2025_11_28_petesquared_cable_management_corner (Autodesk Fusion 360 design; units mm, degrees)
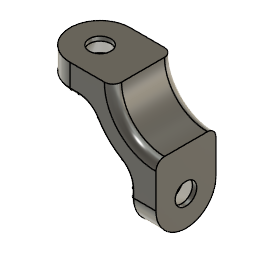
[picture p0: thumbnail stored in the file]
derived_base_feature "Derived Base Feature" bodies "cubby_printer_top", "cubby_printer_side_right"
sketch "cable_bracket_front" plane through (254.762, 0, 0) normal (-1, 0, 0) x axis (0, -1, 0)
  line L1 (0, 15.4952) -> (0, -58.801)
  line L2 (-190.6736, 294.1908) -> (-9.7162, 45.3743)
  line L3 (-9.7162, 662.5237) -> (-190.6736, 413.7072)
  line L4 (0, 766.699) -> (0, 692.4028)
  line L5 (-12.954, 773.049) -> (-6.35, 773.049)
  line L6 (-12.954, 760.095) -> (-12.954, 773.049)
  line L7 (-19.304, 760.095) -> (-12.954, 760.095)
  line L8 (-19.304, 692.4028) -> (-19.304, 760.095)
  line L9 (-31.496, 692.4028) -> (-19.304, 692.4028)
  line L10 (-31.496, 760.095) -> (-31.496, 692.4028)
  line L11 (-584.454, 760.095) -> (-31.496, 760.095)
  line L12 (-584.454, 683.641) -> (-584.454, 760.095)
  line L13 (-596.646, 683.641) -> (-584.454, 683.641)
  line L14 (-596.646, -52.197) -> (-596.646, 683.641)
  line L15 (-12.954, -52.197) -> (-596.646, -52.197)
  line L16 (-12.954, -65.151) -> (-12.954, -52.197)
  line L17 (-6.35, -65.151) -> (-12.954, -65.151)
  line L18 (-583.946, 594.8881) -> (-583.946, 113.0099)
  line L19 (-362.7757, 368.8886) -> (-538.0041, 609.8276)
  line L20 (-538.0041, 98.0704) -> (-362.7757, 339.0094)
  line L21 (-496.0214, 681.6554) -> (-325.3419, 446.9711)
  line L22 (-134.1205, 721.995) -> (-475.4795, 721.995)
  line L23 (-284.2581, 446.9711) -> (-113.5786, 681.6554)
  line L24 (-325.3419, 260.9269) -> (-468.3123, 64.3426)
  line L25 (-141.2877, 64.3426) -> (-284.2581, 260.9269)
  line L26 (-447.7704, 24.003) -> (-161.8296, 24.003)
  line L27 (-128.905, 754.761) -> (-137.795, 754.761)
  line L28 (-128.905, 748.411) -> (-128.905, 754.761)
  line L29 (-137.795, 748.411) -> (-137.795, 754.761)
  line L30 (-128.905, 748.411) -> (-133.35, 748.411)
  line L31 (-137.795, 748.411) -> (-133.35, 748.411)
  line L32 (-133.35, 754.761) -> (-133.35, 748.411)
  line L33 (-128.905, 750.697) -> (-137.795, 750.697)
  line L34 (-31.496, 761.111) -> (-585.216, 761.111)
  arc A1 centre (-6.35, -58.801) radius 6.35 clockwise from (0, -58.801) to (-6.35, -65.151)
  arc A2 centre (-50.8, 15.4952) radius 50.8 clockwise from (-9.7162, 45.3743) to (0, 15.4952)
  arc A3 centre (-108.5061, 353.949) radius 101.6 clockwise from (-190.6736, 294.1908) to (-190.6736, 413.7072)
  arc A4 centre (-50.8, 692.4028) radius 50.8 clockwise from (0, 692.4028) to (-9.7162, 662.5237)
  arc A5 centre (-6.35, 766.699) radius 6.35 clockwise from (-6.35, 773.049) to (0, 766.699)
  circle C1 centre (-76.2, 748.411) radius 1.6002
  circle C2 centre (-133.35, 748.411) radius 1.6002
  circle C3 centre (-190.5, 748.411) radius 1.6002
  circle C4 centre (-247.65, 748.411) radius 1.6002
  circle C5 centre (-361.95, 748.411) radius 1.6002
  circle C6 centre (-419.1, 748.411) radius 1.6002
  circle C7 centre (-476.25, 748.411) radius 1.6002
  circle C8 centre (-533.4, 748.411) radius 1.6002
  circle C9 centre (-304.8, 748.411) radius 1.6002
  circle C10 centre (-533.4, 11.049) radius 8.128
  arc A6 centre (-558.546, 113.0099) radius 25.4 clockwise from (-538.0041, 98.0704) to (-583.946, 113.0099)
  arc A7 centre (-558.546, 594.8881) radius 25.4 clockwise from (-583.946, 594.8881) to (-538.0041, 609.8276)
  arc A8 centre (-383.3176, 353.949) radius 25.4 clockwise from (-362.7757, 368.8886) to (-362.7757, 339.0094)
  arc A9 centre (-304.8, 461.9107) radius 25.4 clockwise from (-284.2581, 446.9711) to (-325.3419, 446.9711)
  arc A10 centre (-475.4795, 696.595) radius 25.4 clockwise from (-496.0214, 681.6554) to (-475.4795, 721.995)
  arc A11 centre (-134.1205, 696.595) radius 25.4 clockwise from (-134.1205, 721.995) to (-113.5786, 681.6554)
  circle C11 centre (-533.4, 696.849) radius 8.128
  circle C12 centre (-76.2, 11.049) radius 8.128
  circle C13 centre (-76.2, 696.849) radius 8.128
  arc A12 centre (-447.7704, 49.403) radius 25.4 clockwise from (-447.7704, 24.003) to (-468.3123, 64.3426)
  arc A13 centre (-304.8, 245.9873) radius 25.4 clockwise from (-325.3419, 260.9269) to (-284.2581, 260.9269)
  arc A14 centre (-161.8296, 49.403) radius 25.4 clockwise from (-141.2877, 64.3426) to (-161.8296, 24.003)
  circle C14 centre (-133.35, 748.411) radius 1.6002
  circle C15 centre (-133.35, 748.411) radius 4.445
  point P74 (-137.795, 748.411)
  point P73 (-128.905, 748.411)
  point P30 (-133.35, 748.411)
  point P75 (-133.35, 748.411)
  point P76 (-128.905, 748.411)
  point P77 (-133.35, 748.411)
  point P78 (-137.795, 748.411)
  point P79 (-133.35, 754.761)
  point P80 (-137.795, 750.697)
  point P81 (-128.905, 750.697)
  point P72 (-128.905, 754.761)
  concentric C14 C15
  parallel L11 L27
  perpendicular L27 L28
  perpendicular L27 L29
  coincident C15 P74
  coincident C15 P73
  coincident P30 P75
  coincident C15 P76
  perpendicular L28 L30
  coincident P73 P76
  coincident P30 P77
  coincident C15 P78
  horizontal L31
  coincident P74 P78
  midpoint L27 P79
  coincident L29 P80
  horizontal L33
  coincident L28 P81
  dimension "d1" diameter C15 = 8.89
  dimension "d2" distance P72 P73 = 6.35
  dimension "d5" distance P72 P81 = 4.064
revolve "Revolve1" sketch "cable_bracket_front" AlongAngle 45
extrude "Extrude1" new body sketch "cable_bracket_front" profile of C2 C14 C15 L27 L28 L29 L33 along normal blind 3.81 bodies "cable_management_corner"
work_plane "WorkPlane3" RotateAngle 45
extrude "Extrude2" cut sketch "cable_bracket_front" profile of C2 C14 blind 12.7 taper 35 from offset 0.635
combine "Combine2"
fillet "Fillet1" radius 3.048 0.508 1.27
mirror "Mirror1" mirrorStitchTolerance 0.1016
named bodies: "cubby_printer_top", "cubby_printer_side_right", "cable_management_corner"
